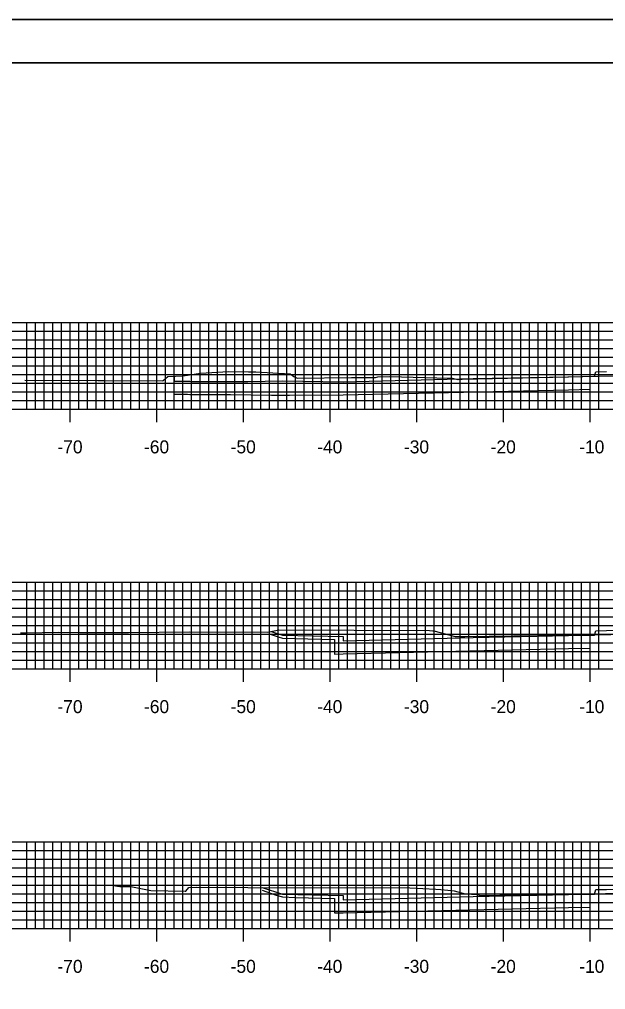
# Model space of a CAD drawing. Extents: x 40011 to 50684, y 49949 to 72236.
# Drawn here: x 41127.3 to 41195, y 71313.9 to 71426 of the extents above; entities that cross this region are included whole.
import ezdxf

# ---------------------------------------------------------------- set-up
doc = ezdxf.new("R2010")
doc.units = 0
for name, color, linetype in [('1', 7, 'Continuous'), ('41', 7, 'Continuous'), ('52', 7, 'Continuous'), ('53', 7, 'Continuous'), ('54', 7, 'Continuous'), ('55', 7, 'Continuous'), ('57', 7, 'Continuous'), ('58', 7, 'Continuous'), ('59', 7, 'Continuous')]:
    doc.layers.add(name, color=color, linetype=linetype)

msp = doc.modelspace()

# ---------------------------------------------------------------- linework, layer by layer
at = {"layer": '1'}
for p, q in [((41384.22, 71425.98), (41034.83, 71425.98)), ((41383.22, 71420.98), (41053.22, 71420.98))]:
    msp.add_line(p, q, dxfattribs=at)
at = {"layer": '41'}
for points in [[(41034.83, 71425.98), (41384.22, 71425.98), (41384.22, 71205.98), (41034.83, 71205.98)], [(41053.22, 71420.98), (41383.22, 71420.98), (41383.22, 71210.98), (41053.22, 71210.98)]]:
    msp.add_lwpolyline(points, close=True, dxfattribs=at)
at = {"layer": '52'}
for p, q in [((41063.22, 71380.98), (41343.22, 71380.98)), ((41133.22, 71379.48), (41133.22, 71380.98)), ((41143.22, 71379.48), (41143.22, 71380.98)), ((41153.22, 71379.48), (41153.22, 71380.98)), ((41163.22, 71379.48), (41163.22, 71380.98)), ((41173.22, 71379.48), (41173.22, 71380.98)), ((41183.22, 71379.48), (41183.22, 71380.98)), ((41193.22, 71379.48), (41193.22, 71380.98)), ((41063.22, 71350.98), (41343.22, 71350.98)), ((41133.22, 71349.48), (41133.22, 71350.98)), ((41143.22, 71349.48), (41143.22, 71350.98)), ((41153.22, 71349.48), (41153.22, 71350.98)), ((41163.22, 71349.48), (41163.22, 71350.98)), ((41173.22, 71349.48), (41173.22, 71350.98)), ((41183.22, 71349.48), (41183.22, 71350.98)), ((41193.22, 71349.48), (41193.22, 71350.98)), ((41063.22, 71320.98), (41343.22, 71320.98)), ((41133.22, 71319.48), (41133.22, 71320.98)), ((41143.22, 71319.48), (41143.22, 71320.98)), ((41153.22, 71319.48), (41153.22, 71320.98)), ((41163.22, 71319.48), (41163.22, 71320.98)), ((41173.22, 71319.48), (41173.22, 71320.98)), ((41183.22, 71319.48), (41183.22, 71320.98)), ((41193.22, 71319.48), (41193.22, 71320.98))]:
    msp.add_line(p, q, dxfattribs=at)
at = {"layer": '53'}
for p, q in [((41063.22, 71389.98), (41343.22, 71389.98)), ((41063.22, 71388.98), (41343.22, 71388.98)), ((41063.22, 71387.98), (41343.22, 71387.98)), ((41063.22, 71386.98), (41343.22, 71386.98)), ((41063.22, 71385.98), (41343.22, 71385.98)), ((41063.22, 71384.98), (41343.22, 71384.98)), ((41063.22, 71383.98), (41343.22, 71383.98)), ((41063.22, 71382.98), (41343.22, 71382.98)), ((41063.22, 71381.98), (41343.22, 71381.98)), ((41063.22, 71359.98), (41343.22, 71359.98)), ((41063.22, 71358.98), (41343.22, 71358.98)), ((41063.22, 71357.98), (41343.22, 71357.98)), ((41063.22, 71356.98), (41343.22, 71356.98)), ((41063.22, 71355.98), (41343.22, 71355.98)), ((41063.22, 71354.98), (41343.22, 71354.98)), ((41063.22, 71353.98), (41343.22, 71353.98)), ((41063.22, 71352.98), (41343.22, 71352.98)), ((41063.22, 71351.98), (41343.22, 71351.98)), ((41063.22, 71329.98), (41343.22, 71329.98)), ((41063.22, 71328.98), (41343.22, 71328.98)), ((41063.22, 71327.98), (41343.22, 71327.98)), ((41063.22, 71326.98), (41343.22, 71326.98)), ((41063.22, 71325.98), (41343.22, 71325.98)), ((41063.22, 71324.98), (41343.22, 71324.98)), ((41063.22, 71323.98), (41343.22, 71323.98)), ((41063.22, 71322.98), (41343.22, 71322.98)), ((41063.22, 71321.98), (41343.22, 71321.98))]:
    msp.add_line(p, q, dxfattribs=at)
at = {"layer": '54'}
for p, q in [((41128.22, 71380.98), (41128.22, 71390.98)), ((41129.22, 71380.98), (41129.22, 71390.98)), ((41130.22, 71380.98), (41130.22, 71390.98)), ((41131.22, 71380.98), (41131.22, 71390.98)), ((41132.22, 71380.98), (41132.22, 71390.98)), ((41134.22, 71380.98), (41134.22, 71390.98)), ((41135.22, 71380.98), (41135.22, 71390.98)), ((41136.22, 71380.98), (41136.22, 71390.98)), ((41137.22, 71380.98), (41137.22, 71390.98)), ((41138.22, 71380.98), (41138.22, 71390.98)), ((41139.22, 71380.98), (41139.22, 71390.98)), ((41140.22, 71380.98), (41140.22, 71390.98)), ((41141.22, 71380.98), (41141.22, 71390.98)), ((41142.22, 71380.98), (41142.22, 71390.98)), ((41144.22, 71380.98), (41144.22, 71390.98)), ((41145.22, 71380.98), (41145.22, 71390.98)), ((41146.22, 71380.98), (41146.22, 71390.98)), ((41147.22, 71380.98), (41147.22, 71390.98)), ((41148.22, 71380.98), (41148.22, 71390.98)), ((41149.22, 71380.98), (41149.22, 71390.98)), ((41150.22, 71380.98), (41150.22, 71390.98)), ((41151.22, 71380.98), (41151.22, 71390.98)), ((41152.22, 71380.98), (41152.22, 71390.98)), ((41154.22, 71380.98), (41154.22, 71390.98)), ((41155.22, 71380.98), (41155.22, 71390.98)), ((41156.22, 71380.98), (41156.22, 71390.98)), ((41157.22, 71380.98), (41157.22, 71390.98)), ((41158.22, 71380.98), (41158.22, 71390.98)), ((41159.22, 71380.98), (41159.22, 71390.98)), ((41160.22, 71380.98), (41160.22, 71390.98)), ((41161.22, 71380.98), (41161.22, 71390.98)), ((41162.22, 71380.98), (41162.22, 71390.98)), ((41164.22, 71380.98), (41164.22, 71390.98)), ((41165.22, 71380.98), (41165.22, 71390.98)), ((41166.22, 71380.98), (41166.22, 71390.98)), ((41167.22, 71380.98), (41167.22, 71390.98)), ((41168.22, 71380.98), (41168.22, 71390.98)), ((41169.22, 71380.98), (41169.22, 71390.98)), ((41170.22, 71380.98), (41170.22, 71390.98)), ((41171.22, 71380.98), (41171.22, 71390.98)), ((41172.22, 71380.98), (41172.22, 71390.98)), ((41174.22, 71380.98), (41174.22, 71390.98)), ((41175.22, 71380.98), (41175.22, 71390.98)), ((41176.22, 71380.98), (41176.22, 71390.98)), ((41177.22, 71380.98), (41177.22, 71390.98)), ((41178.22, 71380.98), (41178.22, 71390.98)), ((41179.22, 71380.98), (41179.22, 71390.98)), ((41180.22, 71380.98), (41180.22, 71390.98)), ((41181.22, 71380.98), (41181.22, 71390.98)), ((41182.22, 71380.98), (41182.22, 71390.98)), ((41184.22, 71380.98), (41184.22, 71390.98)), ((41185.22, 71380.98), (41185.22, 71390.98)), ((41186.22, 71380.98), (41186.22, 71390.98)), ((41187.22, 71380.98), (41187.22, 71390.98)), ((41188.22, 71380.98), (41188.22, 71390.98)), ((41189.22, 71380.98), (41189.22, 71390.98)), ((41190.22, 71380.98), (41190.22, 71390.98)), ((41191.22, 71380.98), (41191.22, 71390.98)), ((41192.22, 71380.98), (41192.22, 71390.98)), ((41194.22, 71380.98), (41194.22, 71390.98)), ((41128.22, 71350.98), (41128.22, 71360.98)), ((41129.22, 71350.98), (41129.22, 71360.98)), ((41130.22, 71350.98), (41130.22, 71360.98)), ((41131.22, 71350.98), (41131.22, 71360.98)), ((41132.22, 71350.98), (41132.22, 71360.98)), ((41134.22, 71350.98), (41134.22, 71360.98)), ((41135.22, 71350.98), (41135.22, 71360.98)), ((41136.22, 71350.98), (41136.22, 71360.98)), ((41137.22, 71350.98), (41137.22, 71360.98)), ((41138.22, 71350.98), (41138.22, 71360.98)), ((41139.22, 71350.98), (41139.22, 71360.98)), ((41140.22, 71350.98), (41140.22, 71360.98)), ((41141.22, 71350.98), (41141.22, 71360.98)), ((41142.22, 71350.98), (41142.22, 71360.98)), ((41144.22, 71350.98), (41144.22, 71360.98)), ((41145.22, 71350.98), (41145.22, 71360.98)), ((41146.22, 71350.98), (41146.22, 71360.98)), ((41147.22, 71350.98), (41147.22, 71360.98)), ((41148.22, 71350.98), (41148.22, 71360.98)), ((41149.22, 71350.98), (41149.22, 71360.98)), ((41150.22, 71350.98), (41150.22, 71360.98)), ((41151.22, 71350.98), (41151.22, 71360.98)), ((41152.22, 71350.98), (41152.22, 71360.98)), ((41154.22, 71350.98), (41154.22, 71360.98)), ((41155.22, 71350.98), (41155.22, 71360.98)), ((41156.22, 71350.98), (41156.22, 71360.98)), ((41157.22, 71350.98), (41157.22, 71360.98)), ((41158.22, 71350.98), (41158.22, 71360.98)), ((41159.22, 71350.98), (41159.22, 71360.98)), ((41160.22, 71350.98), (41160.22, 71360.98)), ((41161.22, 71350.98), (41161.22, 71360.98)), ((41162.22, 71350.98), (41162.22, 71360.98)), ((41164.22, 71350.98), (41164.22, 71360.98)), ((41165.22, 71350.98), (41165.22, 71360.98)), ((41166.22, 71350.98), (41166.22, 71360.98)), ((41167.22, 71350.98), (41167.22, 71360.98)), ((41168.22, 71350.98), (41168.22, 71360.98)), ((41169.22, 71350.98), (41169.22, 71360.98)), ((41170.22, 71350.98), (41170.22, 71360.98)), ((41171.22, 71350.98), (41171.22, 71360.98)), ((41172.22, 71350.98), (41172.22, 71360.98)), ((41174.22, 71350.98), (41174.22, 71360.98)), ((41175.22, 71350.98), (41175.22, 71360.98)), ((41176.22, 71350.98), (41176.22, 71360.98)), ((41177.22, 71350.98), (41177.22, 71360.98)), ((41178.22, 71350.98), (41178.22, 71360.98)), ((41179.22, 71350.98), (41179.22, 71360.98)), ((41180.22, 71350.98), (41180.22, 71360.98)), ((41181.22, 71350.98), (41181.22, 71360.98)), ((41182.22, 71350.98), (41182.22, 71360.98)), ((41184.22, 71350.98), (41184.22, 71360.98)), ((41185.22, 71350.98), (41185.22, 71360.98)), ((41186.22, 71350.98), (41186.22, 71360.98)), ((41187.22, 71350.98), (41187.22, 71360.98)), ((41188.22, 71350.98), (41188.22, 71360.98)), ((41189.22, 71350.98), (41189.22, 71360.98)), ((41190.22, 71350.98), (41190.22, 71360.98)), ((41191.22, 71350.98), (41191.22, 71360.98)), ((41192.22, 71350.98), (41192.22, 71360.98)), ((41194.22, 71350.98), (41194.22, 71360.98)), ((41128.22, 71320.98), (41128.22, 71330.98)), ((41129.22, 71320.98), (41129.22, 71330.98)), ((41130.22, 71320.98), (41130.22, 71330.98)), ((41131.22, 71320.98), (41131.22, 71330.98)), ((41132.22, 71320.98), (41132.22, 71330.98)), ((41134.22, 71320.98), (41134.22, 71330.98)), ((41135.22, 71320.98), (41135.22, 71330.98)), ((41136.22, 71320.98), (41136.22, 71330.98)), ((41137.22, 71320.98), (41137.22, 71330.98)), ((41138.22, 71320.98), (41138.22, 71330.98)), ((41139.22, 71320.98), (41139.22, 71330.98)), ((41140.22, 71320.98), (41140.22, 71330.98)), ((41141.22, 71320.98), (41141.22, 71330.98)), ((41142.22, 71320.98), (41142.22, 71330.98)), ((41144.22, 71320.98), (41144.22, 71330.98)), ((41145.22, 71320.98), (41145.22, 71330.98)), ((41146.22, 71320.98), (41146.22, 71330.98)), ((41147.22, 71320.98), (41147.22, 71330.98)), ((41148.22, 71320.98), (41148.22, 71330.98)), ((41149.22, 71320.98), (41149.22, 71330.98)), ((41150.22, 71320.98), (41150.22, 71330.98)), ((41151.22, 71320.98), (41151.22, 71330.98)), ((41152.22, 71320.98), (41152.22, 71330.98)), ((41154.22, 71320.98), (41154.22, 71330.98)), ((41155.22, 71320.98), (41155.22, 71330.98)), ((41156.22, 71320.98), (41156.22, 71330.98)), ((41157.22, 71320.98), (41157.22, 71330.98)), ((41158.22, 71320.98), (41158.22, 71330.98)), ((41159.22, 71320.98), (41159.22, 71330.98)), ((41160.22, 71320.98), (41160.22, 71330.98)), ((41161.22, 71320.98), (41161.22, 71330.98)), ((41162.22, 71320.98), (41162.22, 71330.98)), ((41164.22, 71320.98), (41164.22, 71330.98)), ((41165.22, 71320.98), (41165.22, 71330.98)), ((41166.22, 71320.98), (41166.22, 71330.98)), ((41167.22, 71320.98), (41167.22, 71330.98)), ((41168.22, 71320.98), (41168.22, 71330.98)), ((41169.22, 71320.98), (41169.22, 71330.98)), ((41170.22, 71320.98), (41170.22, 71330.98)), ((41171.22, 71320.98), (41171.22, 71330.98)), ((41172.22, 71320.98), (41172.22, 71330.98)), ((41174.22, 71320.98), (41174.22, 71330.98)), ((41175.22, 71320.98), (41175.22, 71330.98)), ((41176.22, 71320.98), (41176.22, 71330.98)), ((41177.22, 71320.98), (41177.22, 71330.98)), ((41178.22, 71320.98), (41178.22, 71330.98)), ((41179.22, 71320.98), (41179.22, 71330.98)), ((41180.22, 71320.98), (41180.22, 71330.98)), ((41181.22, 71320.98), (41181.22, 71330.98)), ((41182.22, 71320.98), (41182.22, 71330.98)), ((41184.22, 71320.98), (41184.22, 71330.98)), ((41185.22, 71320.98), (41185.22, 71330.98)), ((41186.22, 71320.98), (41186.22, 71330.98)), ((41187.22, 71320.98), (41187.22, 71330.98)), ((41188.22, 71320.98), (41188.22, 71330.98)), ((41189.22, 71320.98), (41189.22, 71330.98)), ((41190.22, 71320.98), (41190.22, 71330.98)), ((41191.22, 71320.98), (41191.22, 71330.98)), ((41192.22, 71320.98), (41192.22, 71330.98)), ((41194.22, 71320.98), (41194.22, 71330.98))]:
    msp.add_line(p, q, dxfattribs=at)
at = {"layer": '55'}
for p, q in [((41063.22, 71390.98), (41343.22, 71390.98)), ((41133.22, 71380.98), (41133.22, 71390.98)), ((41143.22, 71380.98), (41143.22, 71390.98)), ((41153.22, 71380.98), (41153.22, 71390.98)), ((41163.22, 71380.98), (41163.22, 71390.98)), ((41173.22, 71380.98), (41173.22, 71390.98)), ((41183.22, 71380.98), (41183.22, 71390.98)), ((41193.22, 71380.98), (41193.22, 71390.98)), ((41063.22, 71380.98), (41343.22, 71380.98)), ((41063.22, 71360.98), (41343.22, 71360.98)), ((41133.22, 71350.98), (41133.22, 71360.98)), ((41143.22, 71350.98), (41143.22, 71360.98)), ((41153.22, 71350.98), (41153.22, 71360.98)), ((41163.22, 71350.98), (41163.22, 71360.98)), ((41173.22, 71350.98), (41173.22, 71360.98)), ((41183.22, 71350.98), (41183.22, 71360.98)), ((41193.22, 71350.98), (41193.22, 71360.98)), ((41063.22, 71350.98), (41343.22, 71350.98)), ((41063.22, 71330.98), (41343.22, 71330.98)), ((41133.22, 71320.98), (41133.22, 71330.98)), ((41143.22, 71320.98), (41143.22, 71330.98)), ((41153.22, 71320.98), (41153.22, 71330.98)), ((41163.22, 71320.98), (41163.22, 71330.98)), ((41173.22, 71320.98), (41173.22, 71330.98)), ((41183.22, 71320.98), (41183.22, 71330.98)), ((41193.22, 71320.98), (41193.22, 71330.98)), ((41063.22, 71320.98), (41343.22, 71320.98))]:
    msp.add_line(p, q, dxfattribs=at)
at = {"layer": '57'}
for points in [[(41127.98, 71384.33), (41136.4, 71384.28), (41137.16, 71384.26), (41143.85, 71384.22), (41143.92, 71384.28), (41144.48, 71384.73), (41146.25, 71384.81), (41148.26, 71385.13), (41151.48, 71385.31), (41153.78, 71385.28), (41153.95, 71385.28), (41154.28, 71385.28), (41154.65, 71385.27), (41155.95, 71385.21), (41158.6, 71385.05), (41159.03, 71384.75), (41159.41, 71384.55), (41165.67, 71384.62), (41167.13, 71384.64), (41167.97, 71384.64), (41168.42, 71384.63), (41168.45, 71384.63), (41168.7, 71384.7), (41170.07, 71384.73), (41176.92, 71384.56), (41177, 71384.56), (41177.08, 71384.56), (41177.12, 71384.55), (41177.16, 71384.55), (41177.18, 71384.55), (41177.2, 71384.55), (41177.27, 71384.55), (41177.33, 71384.54), (41177.34, 71384.55), (41177.95, 71384.41), (41177.97, 71384.4), (41178.46, 71384.42), (41204.57, 71384.99)], [(41127.48, 71355.13), (41128.11, 71355.13), (41131.85, 71355.19), (41134.31, 71355.16), (41136.61, 71355.17), (41138, 71355.16), (41138.3, 71355.17), (41139.92, 71355.17), (41146.99, 71355.23), (41156.02, 71355.2), (41157.29, 71355.46), (41174.66, 71355.39), (41175.07, 71355.38), (41175.19, 71355.35), (41177.64, 71354.71), (41177.67, 71354.7), (41178.74, 71354.7), (41204.02, 71355.07)], [(41137.99, 71325.97), (41138.03, 71325.97), (41138.68, 71325.89), (41138.95, 71325.85), (41140.19, 71325.84), (41142.51, 71325.38), (41146.49, 71325.31), (41146.55, 71325.31), (41146.91, 71325.7), (41147.77, 71325.75), (41153.73, 71325.73), (41172.4, 71325.67), (41175.4, 71325.52), (41175.97, 71325.5), (41176.79, 71325.42), (41177.51, 71325.34), (41178.8, 71324.98), (41180.2, 71324.9), (41180.36, 71324.9), (41180.36, 71324.79), (41204.77, 71325.18)]]:
    msp.add_lwpolyline(points, dxfattribs=at)
at = {"layer": '58'}
for points in [[(41145.2, 71382.72), (41145.21, 71382.71), (41145.23, 71382.71), (41145.28, 71382.71), (41145.35, 71382.71), (41145.43, 71382.7), (41145.53, 71382.7), (41145.64, 71382.7), (41145.78, 71382.69), (41145.93, 71382.69), (41146.11, 71382.69), (41146.3, 71382.68), (41146.52, 71382.68), (41146.75, 71382.68), (41147.01, 71382.67), (41147.29, 71382.67), (41147.58, 71382.67), (41147.9, 71382.66), (41148.23, 71382.66), (41148.58, 71382.66), (41148.94, 71382.66), (41149.31, 71382.65), (41149.7, 71382.65), (41150.09, 71382.65), (41150.49, 71382.65), (41150.9, 71382.65), (41151.31, 71382.64), (41151.71, 71382.64), (41156.43, 71382.6), (41156.7, 71382.6), (41156.98, 71382.6), (41157.27, 71382.6), (41157.57, 71382.6), (41157.88, 71382.6), (41158.19, 71382.6), (41158.51, 71382.6), (41164.72, 71382.61), (41176.86, 71382.89), (41190.72, 71383.21), (41190.72, 71383.21), (41193.22, 71383.26)], [(41156.42, 71354.95), (41157.22, 71354.68), (41157.71, 71354.52), (41160.62, 71354.44), (41163.71, 71354.35), (41163.72, 71352.68), (41164.71, 71352.71), (41164.72, 71352.71), (41190.72, 71353.31), (41190.74, 71353.31), (41193.22, 71353.36)], [(41155.38, 71325.4), (41157, 71324.85), (41157.71, 71324.62), (41159.23, 71324.58), (41163.71, 71324.45), (41163.72, 71322.78), (41164.14, 71322.79), (41164.72, 71322.81), (41190.72, 71323.4), (41193.22, 71323.45)]]:
    msp.add_lwpolyline(points, dxfattribs=at)
at = {"layer": '59'}
for points in [[(41145.19, 71384.65), (41145.19, 71384.33), (41145.2, 71384.22), (41145.23, 71384.21), (41145.28, 71384.21), (41145.35, 71384.21), (41145.43, 71384.2), (41145.53, 71384.2), (41145.64, 71384.2), (41145.78, 71384.2), (41145.93, 71384.19), (41146.11, 71384.19), (41146.3, 71384.19), (41146.52, 71384.18), (41146.75, 71384.18), (41147.01, 71384.18), (41147.29, 71384.17), (41147.58, 71384.17), (41147.9, 71384.17), (41148.23, 71384.16), (41148.58, 71384.16), (41148.94, 71384.16), (41152.55, 71384.15), (41152.74, 71384.15), (41152.96, 71384.15), (41153.19, 71384.15), (41153.44, 71384.15), (41153.7, 71384.15), (41157.71, 71384.25), (41164.72, 71384.11), (41179.72, 71384.49), (41190.72, 71384.71), (41193.72, 71384.77), (41193.86, 71385.27), (41193.86, 71385.27), (41195.11, 71385.3)], [(41156.42, 71355.28), (41157.71, 71354.85), (41164.71, 71354.71), (41164.72, 71354.21), (41179.72, 71354.59), (41190.72, 71354.81), (41193.72, 71354.87), (41193.86, 71355.37), (41193.86, 71355.37), (41195.11, 71355.39), (41197.58, 71355.45), (41197.72, 71354.95), (41197.72, 71354.95), (41203.22, 71355.06), (41208.72, 71354.97), (41219.72, 71354.75), (41234.72, 71354.38), (41234.73, 71354.88), (41241.73, 71355.02), (41241.9, 71354.96)], [(41155.38, 71325.73), (41157.71, 71324.95), (41164.71, 71324.81), (41164.72, 71324.31), (41179.72, 71324.68), (41190.72, 71324.9), (41193.72, 71324.96), (41193.86, 71325.47), (41195.11, 71325.49), (41197.58, 71325.54), (41197.72, 71325.04), (41197.72, 71325.05), (41203.22, 71325.15), (41208.72, 71325.07), (41219.72, 71324.85), (41234.72, 71324.48), (41234.73, 71324.98), (41241.73, 71325.12), (41241.78, 71325.14)]]:
    msp.add_lwpolyline(points, dxfattribs=at)

# ---------------------------------------------------------------- texts
at = {"layer": '52'}
for s, p in [('-70', (41131.74, 71375.86)), ('-60', (41141.73, 71375.86)), ('-50', (41151.73, 71375.86)), ('-40', (41161.72, 71375.86)), ('-30', (41171.73, 71375.86)), ('-20', (41181.74, 71375.86)), ('-10', (41191.96, 71375.86)), ('-70', (41131.74, 71345.86)), ('-60', (41141.73, 71345.86)), ('-50', (41151.73, 71345.86)), ('-40', (41161.72, 71345.86)), ('-30', (41171.73, 71345.86)), ('-20', (41181.74, 71345.86)), ('-10', (41191.96, 71345.86)), ('-70', (41131.74, 71315.86)), ('-60', (41141.73, 71315.86)), ('-50', (41151.73, 71315.86)), ('-40', (41161.72, 71315.86)), ('-30', (41171.73, 71315.86)), ('-20', (41181.74, 71315.86)), ('-10', (41191.96, 71315.86))]:
    msp.add_text(s, height=1.5, dxfattribs=at).set_placement(p)

doc.saveas('drawing.dxf')
